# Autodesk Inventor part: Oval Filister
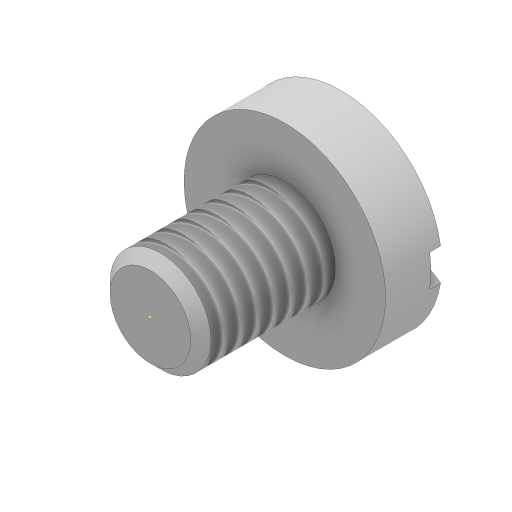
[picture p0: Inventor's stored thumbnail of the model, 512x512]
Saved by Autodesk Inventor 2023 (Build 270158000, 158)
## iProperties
Created: 2016-06
Part Number: Oval Filister
Material: Generic
Document SubType Name: Modeling
Designer: CADCIM
Density: 1 g/cm^3
Appearance: Default
Mass: 0.639925 g
Surface Area: 5.32794 cm^2
Volume: 0.639925 cm^3
Author: CADCIM
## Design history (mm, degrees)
sketch "Sketch1"
  geometry: 1 further point
sketch "Sketch2"
  geometry: C1 r 3 at (0, 0); 1 further point
  constraints: 1 centre point, 1 coincident
  dimensions: "d0" = 6 diameter of C1
extrude "Extrusion1" new body sketch "Sketch2" distance "d1" = 8; taper "d2" = 0 deg
sketch "Sketch3"
  geometry: 1 further point
sketch "Sketch4"
  geometry: L1 (8, 0)-(8, -6); L2 (8, -3)-(8, 3) reference; L3 (8, -6)-(11.35, -6); L4 (12.6, 0)-(8, 0); A1 r 15.025 centre (-2.425, 0) between (11.35, -6) and (12.6, 0); 2 further points
  constraints: 6 end point, 2 midpoint, 2 point on circle, 1 centre point, 1 horizontal, 1 horizontal alignment, 1 perpendicular, 1 point on line, 1 vertical
  dimensions: "d3" = 6 distance of L1.start L1.end; "d4" = 4.6 distance of L4.start L1.start; "d5" = 1.25 horizontal distance of L3.end L4.start
revolve "Revolution1" sketch "Sketch4" stored, may be unused: angle "d6" = 90 deg
workplane "Work Plane1"
sketch "Sketch5"
  geometry: L1 (6.611, -0.95)-(-6.611, -0.95); L2 (-6.611, -0.95)-(-6.611, 0.95); L3 (-6.611, 0.95)-(6.611, 0.95); L4 (6.611, 0.95)-(6.611, -0.95); L5 (6.611, 0)-(-6.611, 0); 2 further points
  constraints: 10 end point, 3 midpoint, 2 parallel, 1 coincident, 1 horizontal, 1 perpendicular
  dimensions: "d8" = 1.9 distance of L3.end L1.start
extrude "Extrusion2" cut sketch "Sketch5" distance "d9" = 1.9; taper "d10" = 0 deg
thread "Thread1" dims "d11" = 10, "d12" = 0
chamfer "Chamfer1" distance "d13" = 0.6; stored, may be unused: second distance "d14" = 2, angle "d15" = 45 deg
body "Solid1"
other parameters: "d7" = -4.6
